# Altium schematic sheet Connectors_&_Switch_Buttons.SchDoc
size 431 x 279 mm; Organization: ORGANIZATION; Address1: ADDRESS 1; Address2: ADDRESS 2; Address3: ADDRESS 3; Address4: ADDRESS 4; Revision: -; SheetNumber: 3; SheetTotal: 4; ENG_APP_DATE: --/--/--; DSN_APP_DATE: --/--/--; CHK_APP_DATE: --/--/--
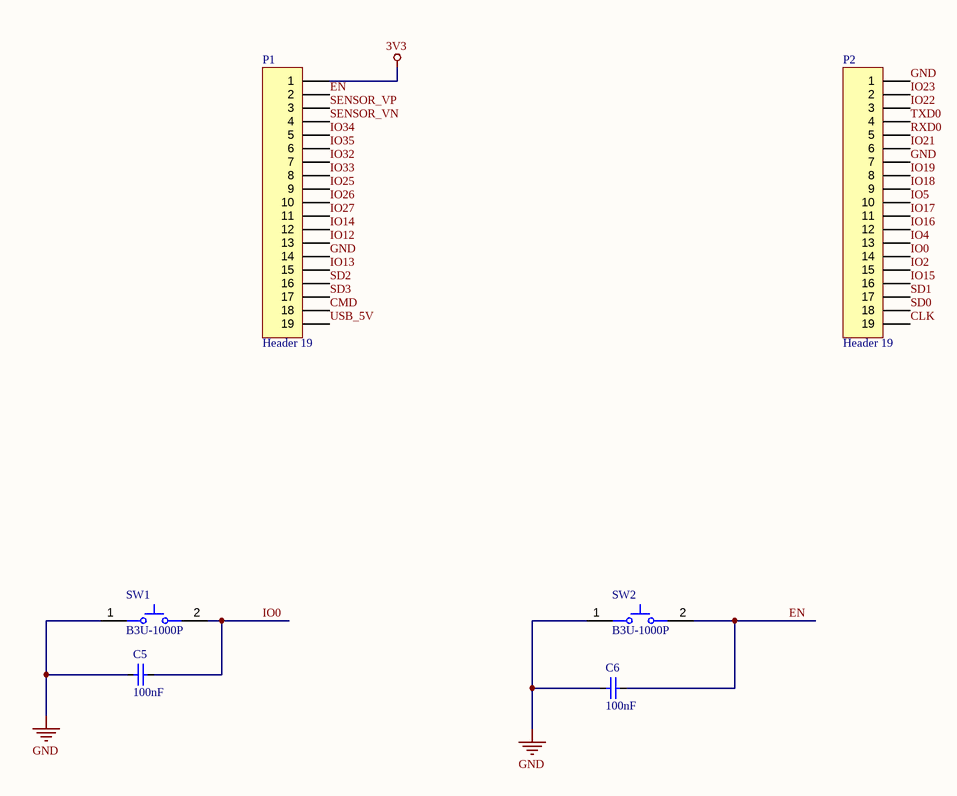
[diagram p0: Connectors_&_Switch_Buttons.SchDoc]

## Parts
C5  value 100nF  [0603C_L]  (hidden comment: Cap100nF_50V_0603)
C6  value 100nF  [0603C_L]  (hidden comment: Cap100nF_50V_0603)
P1  Header 19  [HDR1X19]
P2  Header 19  [HDR1X19]
SW1  B3U-1000P  [OMRON-B3U-1000_V]
SW2  B3U-1000P  [OMRON-B3U-1000_V]

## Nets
3V3: P1.1
GND: C5.1 C6.1 P1.14 P2.1 P2.7 SW1.1 SW2.1
CLK: P2.19
CMD: P1.18
EN: C6.2 P1.2 SW2.2
IO0: C5.2 P2.14 SW1.2
IO2: P2.15
IO4: P2.13
IO5: P2.10
IO12: P1.13
IO13: P1.15
IO14: P1.12
IO15: P2.16
IO16: P2.12
IO17: P2.11
IO18: P2.9
IO19: P2.8
IO21: P2.6
IO22: P2.3
IO23: P2.2
IO25: P1.9
IO26: P1.10
IO27: P1.11
IO32: P1.7
IO33: P1.8
IO34: P1.5
IO35: P1.6
RXD0: P2.5
SD0: P2.18
SD1: P2.17
SD2: P1.16
SD3: P1.17
SENSOR_VN: P1.4
SENSOR_VP: P1.3
TXD0: P2.4
USB_5V: P1.19

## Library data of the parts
C5 C6 = CMP-001-00084-1: Ceramic Capacitor, Multilayer, Ceramic, 50V, 80% +Tol, 20% -Tol, Y5V, -82/+22% TC, 0.1uF, Surface Mount, 0603; Manufacturer: Yageo; Manufacturer Part Number: CC0603ZRY5V9BB104; Multilayer: Yes
P1 P2 = Header 19: Header, 19-Pin
SW1 SW2 = CMP-011-00000-2: Tactile Switch, SPST-NO, 0.05 A, 12 V, -25 to 70 degC, 2-Pin SMD, RoHS, Tape and Reel; Manufacturer: Omron Electronic Components; IP Rating: IP40; Current Rating: 50mA; Max Contact Resistance: 100mohm; Operating Force: 153gf; Throw Configuration: SPST; Resistance: 0.1Ohm; Max Voltage Rating (DC): 12V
